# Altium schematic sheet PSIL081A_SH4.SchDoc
size 558 x 431 mm; Date: Not shown in title block; ApprovedBy: Not shown in title block; CheckedBy: Not shown in title block; Author: Not shown in title block; CompanyName: Not shown in title block; Engineer: Not shown in title block; Organization: Not shown in title block; Address1: Not shown in title block; Address2: Not shown in title block; Address3: Not shown in title block; Address4: Not shown in title block; DocumentNumber: 4; Revision: Use project parameter SCH_Rev; SheetNumber: 4; SheetTotal: 5; PageSetup: Record=PageOptions¦CenterHorizontal=True¦CenterVertical=True¦PrintScale=1.00¦XCorrection=1.00¦YCorrection=1.00¦PrintKind=0¦BorderSize=5000000¦LeftOffset=0¦BottomOffset=0¦Orientation=2¦PaperLength=1000¦PaperWidth=1000¦Scale=100¦PaperSource=15¦PrintQuality=600¦MediaType=1¦DitherType=10¦PaperKind=Letter¦PrintScaleMode=1
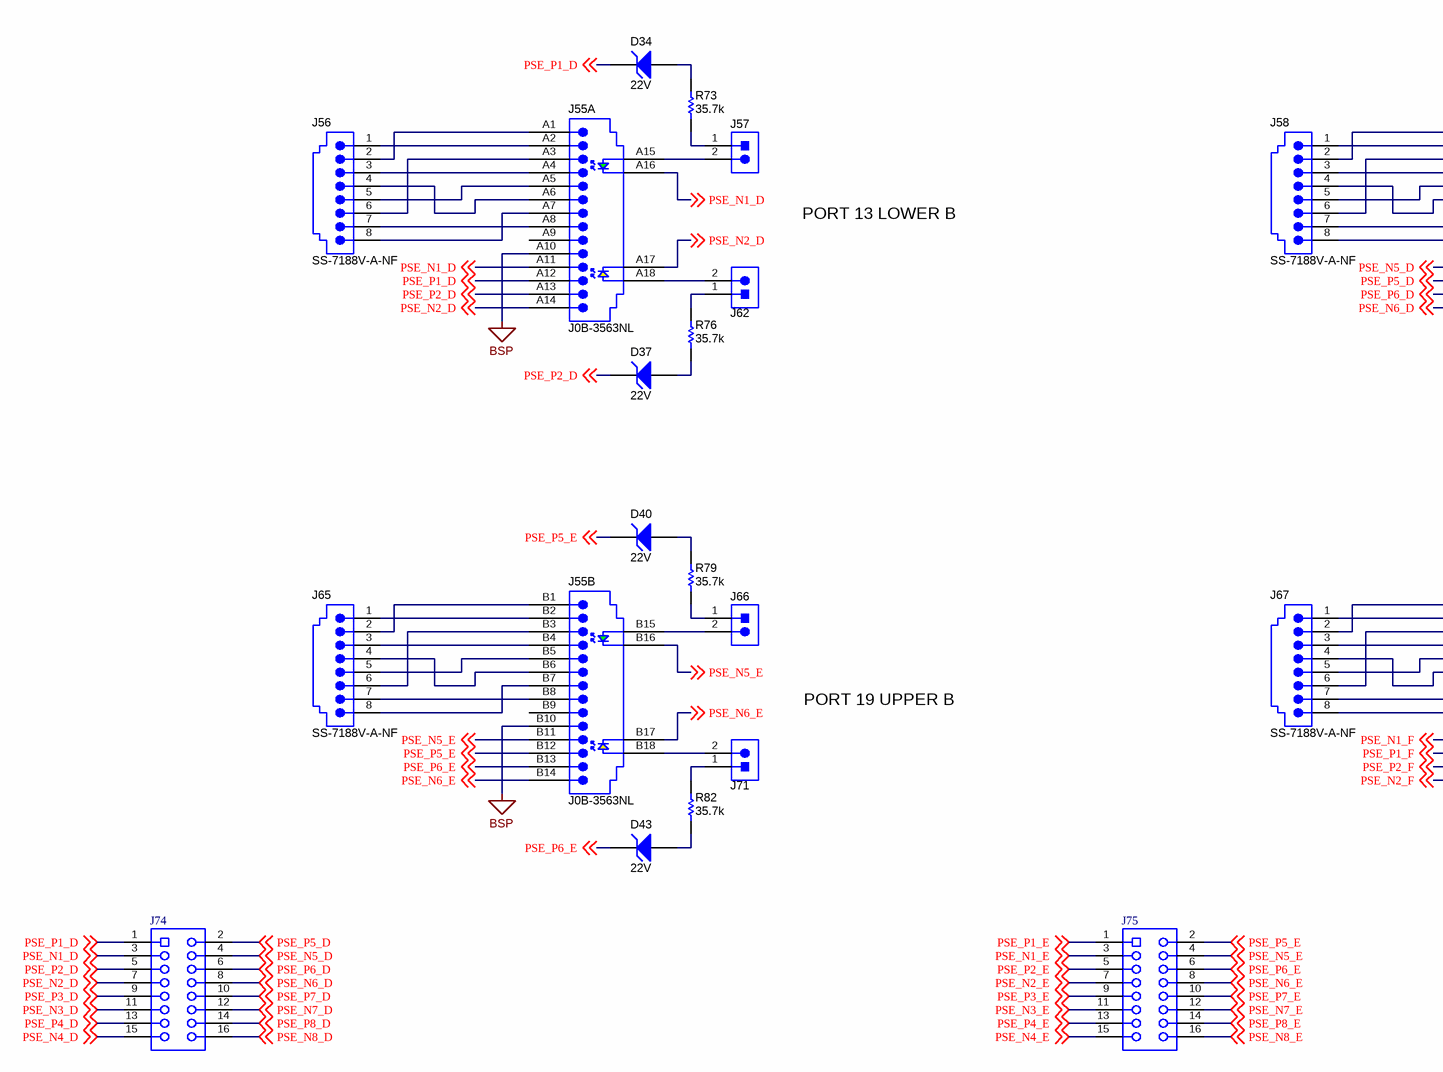
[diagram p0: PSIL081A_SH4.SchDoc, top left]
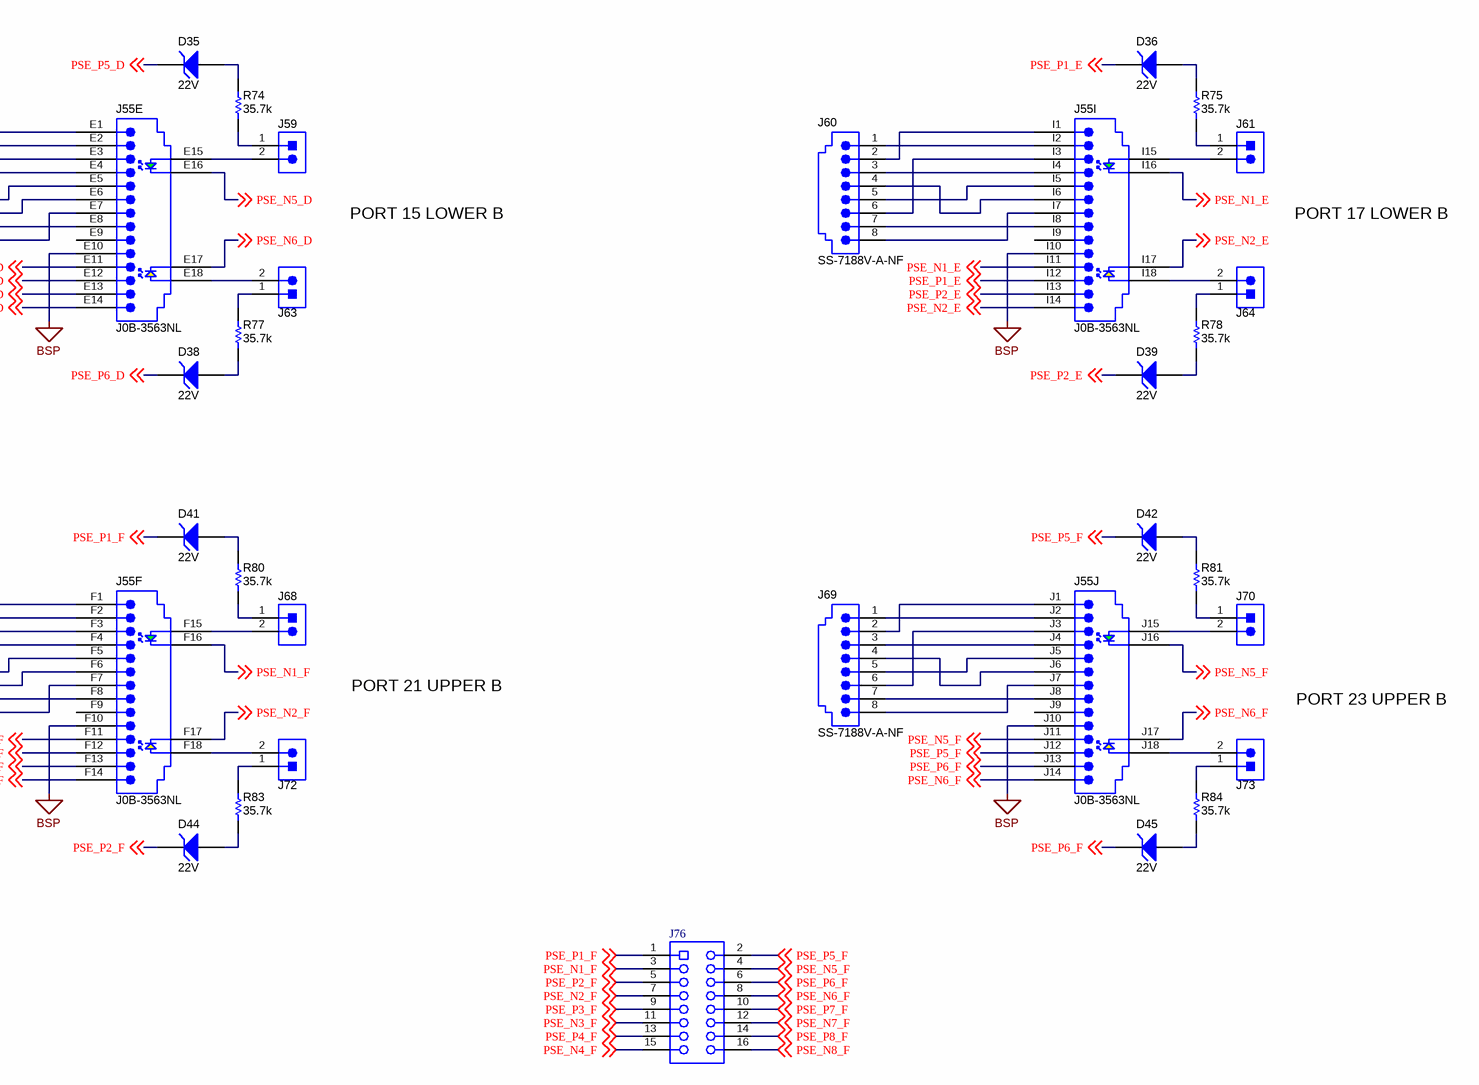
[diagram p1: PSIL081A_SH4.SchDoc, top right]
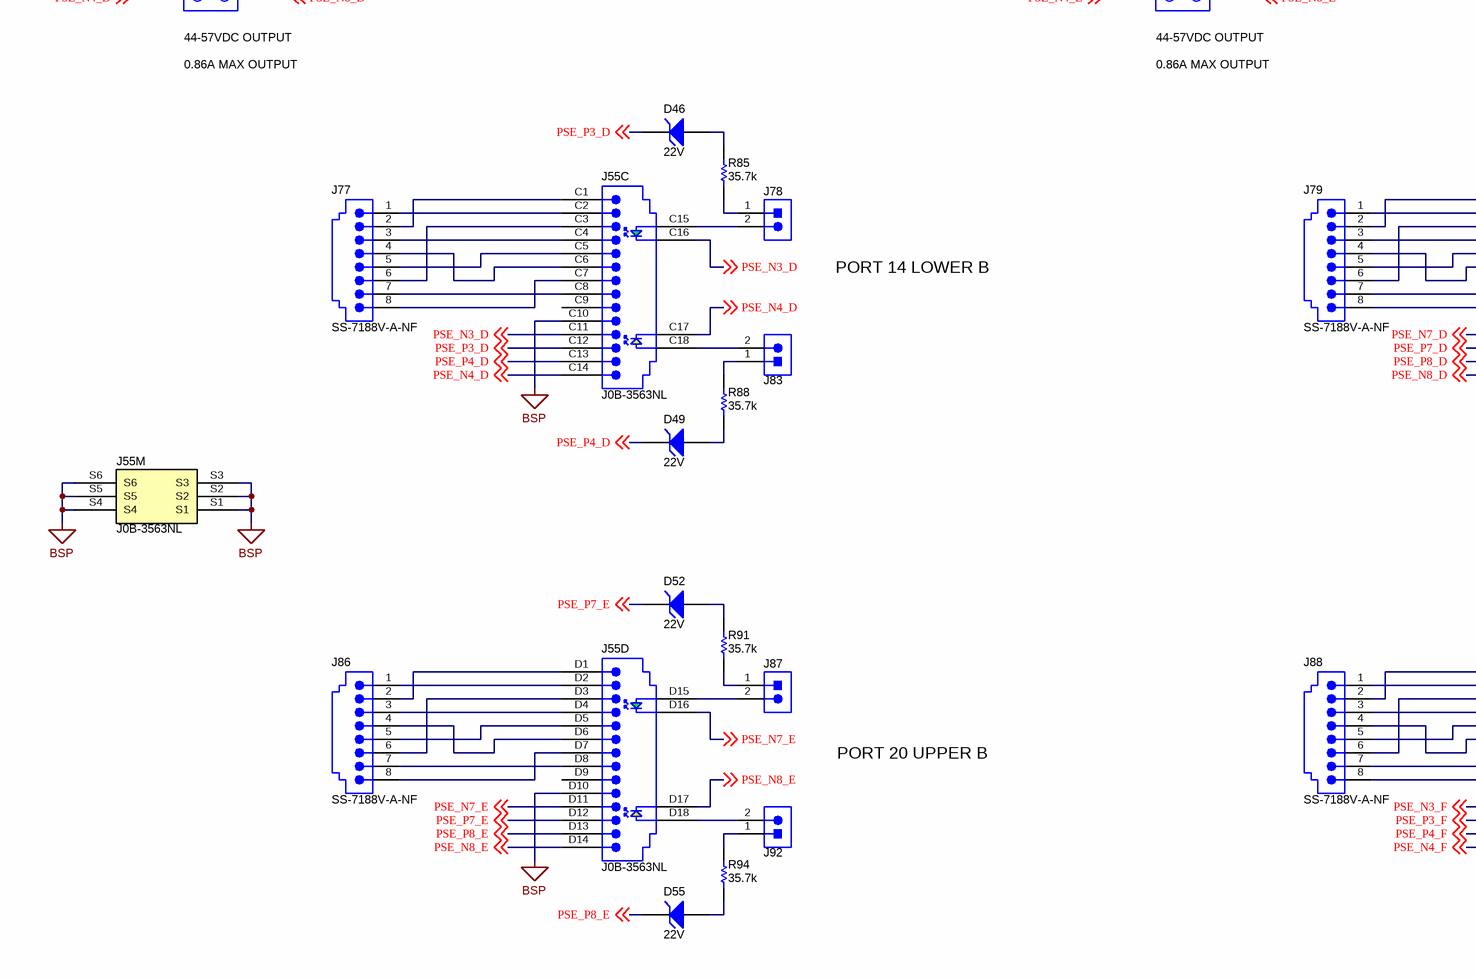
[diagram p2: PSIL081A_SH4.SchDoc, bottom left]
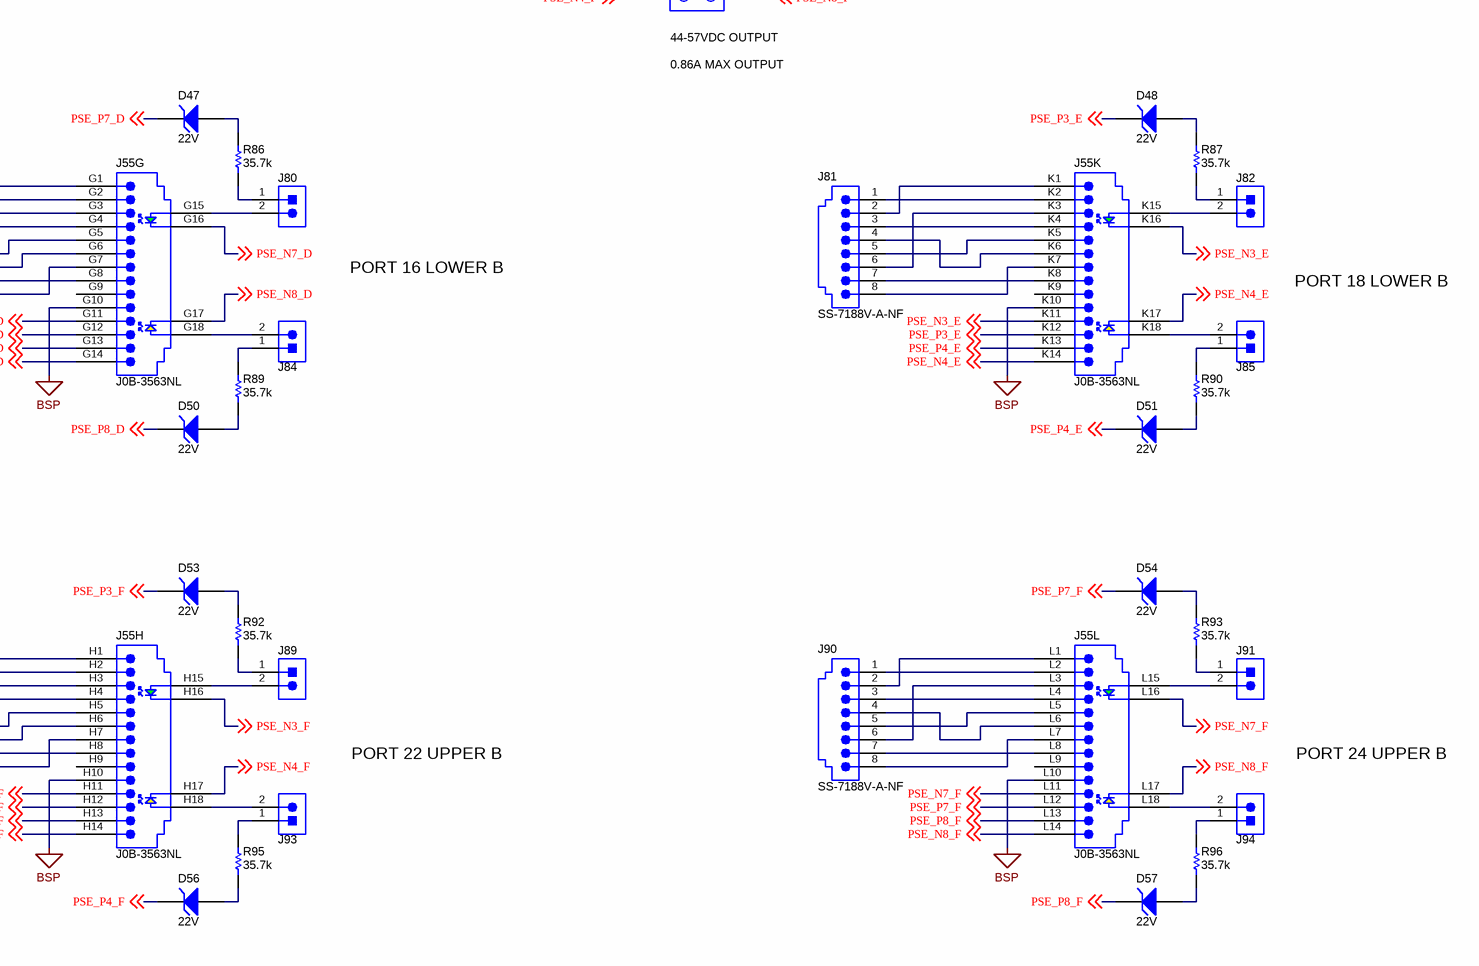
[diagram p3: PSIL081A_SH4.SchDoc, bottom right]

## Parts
D34  Vz_V: 22V  [SOD-123]  (hidden comment: MMSZ5251B-7-F)
D35  Vz_V: 22V  [SOD-123]  (hidden comment: MMSZ5251B-7-F)
D36  Vz_V: 22V  [SOD-123]  (hidden comment: MMSZ5251B-7-F)
D37  Vz_V: 22V  [SOD-123]  (hidden comment: MMSZ5251B-7-F)
D38  Vz_V: 22V  [SOD-123]  (hidden comment: MMSZ5251B-7-F)
D39  Vz_V: 22V  [SOD-123]  (hidden comment: MMSZ5251B-7-F)
D40  Vz_V: 22V  [SOD-123]  (hidden comment: MMSZ5251B-7-F)
D41  Vz_V: 22V  [SOD-123]  (hidden comment: MMSZ5251B-7-F)
D42  Vz_V: 22V  [SOD-123]  (hidden comment: MMSZ5251B-7-F)
D43  Vz_V: 22V  [SOD-123]  (hidden comment: MMSZ5251B-7-F)
D44  Vz_V: 22V  [SOD-123]  (hidden comment: MMSZ5251B-7-F)
D45  Vz_V: 22V  [SOD-123]  (hidden comment: MMSZ5251B-7-F)
D46  Vz_V: 22V  [SOD-123]  (hidden comment: MMSZ5251B-7-F)
D47  Vz_V: 22V  [SOD-123]  (hidden comment: MMSZ5251B-7-F)
D48  Vz_V: 22V  [SOD-123]  (hidden comment: MMSZ5251B-7-F)
D49  Vz_V: 22V  [SOD-123]  (hidden comment: MMSZ5251B-7-F)
D50  Vz_V: 22V  [SOD-123]  (hidden comment: MMSZ5251B-7-F)
D51  Vz_V: 22V  [SOD-123]  (hidden comment: MMSZ5251B-7-F)
D52  Vz_V: 22V  [SOD-123]  (hidden comment: MMSZ5251B-7-F)
D53  Vz_V: 22V  [SOD-123]  (hidden comment: MMSZ5251B-7-F)
D54  Vz_V: 22V  [SOD-123]  (hidden comment: MMSZ5251B-7-F)
D55  Vz_V: 22V  [SOD-123]  (hidden comment: MMSZ5251B-7-F)
D56  Vz_V: 22V  [SOD-123]  (hidden comment: MMSZ5251B-7-F)
D57  Vz_V: 22V  [SOD-123]  (hidden comment: MMSZ5251B-7-F)
J55  J0B-3563NL  [Pulse_J0B-3563NL]  (parts A,B,C,D,E,F,G,H,I,J,K,L,M of 13)
J56  SS-7188V-A-NF  [CONN_SS-7188V-A-NF]
J57  TSW-102-07-G-S  [TSW-102-07-G-S]  (value not drawn)
J58  SS-7188V-A-NF  [CONN_SS-7188V-A-NF]
J59  TSW-102-07-G-S  [TSW-102-07-G-S]  (value not drawn)
J60  SS-7188V-A-NF  [CONN_SS-7188V-A-NF]
J61  TSW-102-07-G-S  [TSW-102-07-G-S]  (value not drawn)
J62  TSW-102-07-G-S  [TSW-102-07-G-S]  (value not drawn)
J63  TSW-102-07-G-S  [TSW-102-07-G-S]  (value not drawn)
J64  TSW-102-07-G-S  [TSW-102-07-G-S]  (value not drawn)
J65  SS-7188V-A-NF  [CONN_SS-7188V-A-NF]
J66  TSW-102-07-G-S  [TSW-102-07-G-S]  (value not drawn)
J67  SS-7188V-A-NF  [CONN_SS-7188V-A-NF]
J68  TSW-102-07-G-S  [TSW-102-07-G-S]  (value not drawn)
J69  SS-7188V-A-NF  [CONN_SS-7188V-A-NF]
J70  TSW-102-07-G-S  [TSW-102-07-G-S]  (value not drawn)
J71  TSW-102-07-G-S  [TSW-102-07-G-S]  (value not drawn)
J72  TSW-102-07-G-S  [TSW-102-07-G-S]  (value not drawn)
J73  TSW-102-07-G-S  [TSW-102-07-G-S]  (value not drawn)
J74  SSW-108-21-G-D  [Samtec_SSW-108-01-x-D]  (value not drawn)
J75  SSW-108-21-G-D  [Samtec_SSW-108-01-x-D]  (value not drawn)
J76  SSW-108-21-G-D  [Samtec_SSW-108-01-x-D]  (value not drawn)
J77  SS-7188V-A-NF  [CONN_SS-7188V-A-NF]
J78  TSW-102-07-G-S  [TSW-102-07-G-S]  (value not drawn)
J79  SS-7188V-A-NF  [CONN_SS-7188V-A-NF]
J80  TSW-102-07-G-S  [TSW-102-07-G-S]  (value not drawn)
J81  SS-7188V-A-NF  [CONN_SS-7188V-A-NF]
J82  TSW-102-07-G-S  [TSW-102-07-G-S]  (value not drawn)
J83  TSW-102-07-G-S  [TSW-102-07-G-S]  (value not drawn)
J84  TSW-102-07-G-S  [TSW-102-07-G-S]  (value not drawn)
J85  TSW-102-07-G-S  [TSW-102-07-G-S]  (value not drawn)
J86  SS-7188V-A-NF  [CONN_SS-7188V-A-NF]
J87  TSW-102-07-G-S  [TSW-102-07-G-S]  (value not drawn)
J88  SS-7188V-A-NF  [CONN_SS-7188V-A-NF]
J89  TSW-102-07-G-S  [TSW-102-07-G-S]  (value not drawn)
J90  SS-7188V-A-NF  [CONN_SS-7188V-A-NF]
J91  TSW-102-07-G-S  [TSW-102-07-G-S]  (value not drawn)
J92  TSW-102-07-G-S  [TSW-102-07-G-S]  (value not drawn)
J93  TSW-102-07-G-S  [TSW-102-07-G-S]  (value not drawn)
J94  TSW-102-07-G-S  [TSW-102-07-G-S]  (value not drawn)
R73  ValueDisplayed: 35.7k  [0603]  (hidden comment: CRCW060335K7FKEA)
R74  ValueDisplayed: 35.7k  [0603]  (hidden comment: CRCW060335K7FKEA)
R75  ValueDisplayed: 35.7k  [0603]  (hidden comment: CRCW060335K7FKEA)
R76  ValueDisplayed: 35.7k  [0603]  (hidden comment: CRCW060335K7FKEA)
R77  ValueDisplayed: 35.7k  [0603]  (hidden comment: CRCW060335K7FKEA)
R78  ValueDisplayed: 35.7k  [0603]  (hidden comment: CRCW060335K7FKEA)
R79  ValueDisplayed: 35.7k  [0603]  (hidden comment: CRCW060335K7FKEA)
R80  ValueDisplayed: 35.7k  [0603]  (hidden comment: CRCW060335K7FKEA)
R81  ValueDisplayed: 35.7k  [0603]  (hidden comment: CRCW060335K7FKEA)
R82  ValueDisplayed: 35.7k  [0603]  (hidden comment: CRCW060335K7FKEA)
R83  ValueDisplayed: 35.7k  [0603]  (hidden comment: CRCW060335K7FKEA)
R84  ValueDisplayed: 35.7k  [0603]  (hidden comment: CRCW060335K7FKEA)
R85  ValueDisplayed: 35.7k  [0603]  (hidden comment: CRCW060335K7FKEA)
R86  ValueDisplayed: 35.7k  [0603]  (hidden comment: CRCW060335K7FKEA)
R87  ValueDisplayed: 35.7k  [0603]  (hidden comment: CRCW060335K7FKEA)
R88  ValueDisplayed: 35.7k  [0603]  (hidden comment: CRCW060335K7FKEA)
R89  ValueDisplayed: 35.7k  [0603]  (hidden comment: CRCW060335K7FKEA)
R90  ValueDisplayed: 35.7k  [0603]  (hidden comment: CRCW060335K7FKEA)
R91  ValueDisplayed: 35.7k  [0603]  (hidden comment: CRCW060335K7FKEA)
R92  ValueDisplayed: 35.7k  [0603]  (hidden comment: CRCW060335K7FKEA)
R93  ValueDisplayed: 35.7k  [0603]  (hidden comment: CRCW060335K7FKEA)
R94  ValueDisplayed: 35.7k  [0603]  (hidden comment: CRCW060335K7FKEA)
R95  ValueDisplayed: 35.7k  [0603]  (hidden comment: CRCW060335K7FKEA)
R96  ValueDisplayed: 35.7k  [0603]  (hidden comment: CRCW060335K7FKEA)

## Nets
BSP: J55.A10 J55.B10 J55.C10 J55.D10 J55.E10 J55.F10 J55.G10 J55.H10 J55.I10 J55.J10 J55.K10 J55.L10 J55.S1 J55.S2 J55.S3 J55.S4 J55.S5 J55.S6
PSE_N1_D: J55.A11 J55.A16 J74.3 ; off-sheet PSE_N1_D
PSE_N1_E: J55.I11 J55.I16 J75.3 ; off-sheet PSE_N1_E
PSE_N1_F: J55.F11 J55.F16 J76.3 ; off-sheet PSE_N1_F
PSE_N2_D: J55.A14 J55.A17 J74.7 ; off-sheet PSE_N2_D
PSE_N2_E: J55.I14 J55.I17 J75.7 ; off-sheet PSE_N2_E
PSE_N2_F: J55.F14 J55.F17 J76.7 ; off-sheet PSE_N2_F
PSE_N3_D: J55.C11 J55.C16 J74.11 ; off-sheet PSE_N3_D
PSE_N3_E: J55.K11 J55.K16 J75.11 ; off-sheet PSE_N3_E
PSE_N3_F: J55.H11 J55.H16 J76.11 ; off-sheet PSE_N3_F
PSE_N4_D: J55.C14 J55.C17 J74.15 ; off-sheet PSE_N4_D
PSE_N4_E: J55.K14 J55.K17 J75.15 ; off-sheet PSE_N4_E
PSE_N4_F: J55.H14 J55.H17 J76.15 ; off-sheet PSE_N4_F
PSE_N5_D: J55.E11 J55.E16 J74.4 ; off-sheet PSE_N5_D
PSE_N5_E: J55.B11 J55.B16 J75.4 ; off-sheet PSE_N5_E
PSE_N5_F: J55.J11 J55.J16 J76.4 ; off-sheet PSE_N5_F
PSE_N6_D: J55.E14 J55.E17 J74.8 ; off-sheet PSE_N6_D
PSE_N6_E: J55.B14 J55.B17 J75.8 ; off-sheet PSE_N6_E
PSE_N6_F: J55.J14 J55.J17 J76.8 ; off-sheet PSE_N6_F
PSE_N7_D: J55.G11 J55.G16 J74.12 ; off-sheet PSE_N7_D
PSE_N7_E: J55.D11 J55.D16 J75.12 ; off-sheet PSE_N7_E
PSE_N7_F: J55.L11 J55.L16 J76.12 ; off-sheet PSE_N7_F
PSE_N8_D: J55.G14 J55.G17 J74.16 ; off-sheet PSE_N8_D
PSE_N8_E: J55.D14 J55.D17 J75.16 ; off-sheet PSE_N8_E
PSE_N8_F: J55.L14 J55.L17 J76.16 ; off-sheet PSE_N8_F
PSE_P1_D: D34.1(K) J55.A12 J74.1 ; off-sheet PSE_P1_D
PSE_P1_E: D36.1(K) J55.I12 J75.1 ; off-sheet PSE_P1_E
PSE_P1_F: D41.1(K) J55.F12 J76.1 ; off-sheet PSE_P1_F
PSE_P2_D: D37.1(K) J55.A13 J74.5 ; off-sheet PSE_P2_D
PSE_P2_E: D39.1(K) J55.I13 J75.5 ; off-sheet PSE_P2_E
PSE_P2_F: D44.1(K) J55.F13 J76.5 ; off-sheet PSE_P2_F
PSE_P3_D: D46.1(K) J55.C12 J74.9 ; off-sheet PSE_P3_D
PSE_P3_E: D48.1(K) J55.K12 J75.9 ; off-sheet PSE_P3_E
PSE_P3_F: D53.1(K) J55.H12 J76.9 ; off-sheet PSE_P3_F
PSE_P4_D: D49.1(K) J55.C13 J74.13 ; off-sheet PSE_P4_D
PSE_P4_E: D51.1(K) J55.K13 J75.13 ; off-sheet PSE_P4_E
PSE_P4_F: D56.1(K) J55.H13 J76.13 ; off-sheet PSE_P4_F
PSE_P5_D: D35.1(K) J55.E12 J74.2 ; off-sheet PSE_P5_D
PSE_P5_E: D40.1(K) J55.B12 J75.2 ; off-sheet PSE_P5_E
PSE_P5_F: D42.1(K) J55.J12 J76.2 ; off-sheet PSE_P5_F
PSE_P6_D: D38.1(K) J55.E13 J74.6 ; off-sheet PSE_P6_D
PSE_P6_E: D43.1(K) J55.B13 J75.6 ; off-sheet PSE_P6_E
PSE_P6_F: D45.1(K) J55.J13 J76.6 ; off-sheet PSE_P6_F
PSE_P7_D: D47.1(K) J55.G12 J74.10 ; off-sheet PSE_P7_D
PSE_P7_E: D52.1(K) J55.D12 J75.10 ; off-sheet PSE_P7_E
PSE_P7_F: D54.1(K) J55.L12 J76.10 ; off-sheet PSE_P7_F
PSE_P8_D: D50.1(K) J55.G13 J74.14 ; off-sheet PSE_P8_D
PSE_P8_E: D55.1(K) J55.D13 J75.14 ; off-sheet PSE_P8_E
PSE_P8_F: D57.1(K) J55.L13 J76.14 ; off-sheet PSE_P8_F
NetD34_2: D34.2(A) R73.1
NetD35_2: D35.2(A) R74.1
NetD36_2: D36.2(A) R75.1
NetD37_2: D37.2(A) R76.2
NetD38_2: D38.2(A) R77.2
NetD39_2: D39.2(A) R78.2
NetD40_2: D40.2(A) R79.1
NetD41_2: D41.2(A) R80.1
NetD42_2: D42.2(A) R81.1
NetD43_2: D43.2(A) R82.2
NetD44_2: D44.2(A) R83.2
NetD45_2: D45.2(A) R84.2
NetD46_2: D46.2(A) R85.1
NetD47_2: D47.2(A) R86.1
NetD48_2: D48.2(A) R87.1
NetD49_2: D49.2(A) R88.2
NetD50_2: D50.2(A) R89.2
NetD51_2: D51.2(A) R90.2
NetD52_2: D52.2(A) R91.1
NetD53_2: D53.2(A) R92.1
NetD54_2: D54.2(A) R93.1
NetD55_2: D55.2(A) R94.2
NetD56_2: D56.2(A) R95.2
NetD57_2: D57.2(A) R96.2
NetJ55_A1: J55.A1 J56.2
NetJ55_A2: J55.A2 J56.1
NetJ55_A3: J55.A3 J56.6
NetJ55_A4: J55.A4 J56.3
NetJ55_A5: J55.A5 J56.5
NetJ55_A6: J55.A6 J56.4
NetJ55_A7: J55.A7 J56.8
NetJ55_A8: J55.A8 J56.7
NetJ55_A15: J55.A15 J57.2
NetJ55_A18: J55.A18 J62.2
NetJ55_B1: J55.B1 J65.2
NetJ55_B2: J55.B2 J65.1
NetJ55_B3: J55.B3 J65.6
NetJ55_B4: J55.B4 J65.3
NetJ55_B5: J55.B5 J65.5
NetJ55_B6: J55.B6 J65.4
NetJ55_B7: J55.B7 J65.8
NetJ55_B8: J55.B8 J65.7
NetJ55_B15: J55.B15 J66.2
NetJ55_B18: J55.B18 J71.2
NetJ55_C1: J55.C1 J77.2
NetJ55_C2: J55.C2 J77.1
NetJ55_C3: J55.C3 J77.6
NetJ55_C4: J55.C4 J77.3
NetJ55_C5: J55.C5 J77.5
NetJ55_C6: J55.C6 J77.4
NetJ55_C7: J55.C7 J77.8
NetJ55_C8: J55.C8 J77.7
NetJ55_C15: J55.C15 J78.2
NetJ55_C18: J55.C18 J83.2
NetJ55_D1: J55.D1 J86.2
NetJ55_D2: J55.D2 J86.1
NetJ55_D3: J55.D3 J86.6
NetJ55_D4: J55.D4 J86.3
NetJ55_D5: J55.D5 J86.5
NetJ55_D6: J55.D6 J86.4
NetJ55_D7: J55.D7 J86.8
NetJ55_D8: J55.D8 J86.7
NetJ55_D15: J55.D15 J87.2
NetJ55_D18: J55.D18 J92.2
NetJ55_E1: J55.E1 J58.2
NetJ55_E2: J55.E2 J58.1
NetJ55_E3: J55.E3 J58.6
NetJ55_E4: J55.E4 J58.3
NetJ55_E5: J55.E5 J58.5
NetJ55_E6: J55.E6 J58.4
NetJ55_E7: J55.E7 J58.8
NetJ55_E8: J55.E8 J58.7
NetJ55_E15: J55.E15 J59.2
NetJ55_E18: J55.E18 J63.2
NetJ55_F1: J55.F1 J67.2
NetJ55_F2: J55.F2 J67.1
NetJ55_F3: J55.F3 J67.6
NetJ55_F4: J55.F4 J67.3
NetJ55_F5: J55.F5 J67.5
NetJ55_F6: J55.F6 J67.4
NetJ55_F7: J55.F7 J67.8
NetJ55_F8: J55.F8 J67.7
NetJ55_F15: J55.F15 J68.2
NetJ55_F18: J55.F18 J72.2
NetJ55_G1: J55.G1 J79.2
NetJ55_G2: J55.G2 J79.1
NetJ55_G3: J55.G3 J79.6
NetJ55_G4: J55.G4 J79.3
NetJ55_G5: J55.G5 J79.5
NetJ55_G6: J55.G6 J79.4
NetJ55_G7: J55.G7 J79.8
NetJ55_G8: J55.G8 J79.7
NetJ55_G15: J55.G15 J80.2
NetJ55_G18: J55.G18 J84.2
NetJ55_H1: J55.H1 J88.2
NetJ55_H2: J55.H2 J88.1
NetJ55_H3: J55.H3 J88.6
NetJ55_H4: J55.H4 J88.3
NetJ55_H5: J55.H5 J88.5
NetJ55_H6: J55.H6 J88.4
NetJ55_H7: J55.H7 J88.8
NetJ55_H8: J55.H8 J88.7
NetJ55_H15: J55.H15 J89.2
NetJ55_H18: J55.H18 J93.2
NetJ55_I1: J55.I1 J60.2
NetJ55_I2: J55.I2 J60.1
NetJ55_I3: J55.I3 J60.6
NetJ55_I4: J55.I4 J60.3
NetJ55_I5: J55.I5 J60.5
NetJ55_I6: J55.I6 J60.4
NetJ55_I7: J55.I7 J60.8
NetJ55_I8: J55.I8 J60.7
NetJ55_I15: J55.I15 J61.2
NetJ55_I18: J55.I18 J64.2
NetJ55_J1: J55.J1 J69.2
NetJ55_J2: J55.J2 J69.1
NetJ55_J3: J55.J3 J69.6
NetJ55_J4: J55.J4 J69.3
NetJ55_J5: J55.J5 J69.5
NetJ55_J6: J55.J6 J69.4
NetJ55_J7: J55.J7 J69.8
NetJ55_J8: J55.J8 J69.7
NetJ55_J15: J55.J15 J70.2
NetJ55_J18: J55.J18 J73.2
NetJ55_K1: J55.K1 J81.2
NetJ55_K2: J55.K2 J81.1
NetJ55_K3: J55.K3 J81.6
NetJ55_K4: J55.K4 J81.3
NetJ55_K5: J55.K5 J81.5
NetJ55_K6: J55.K6 J81.4
NetJ55_K7: J55.K7 J81.8
NetJ55_K8: J55.K8 J81.7
NetJ55_K15: J55.K15 J82.2
NetJ55_K18: J55.K18 J85.2
NetJ55_L1: J55.L1 J90.2
NetJ55_L2: J55.L2 J90.1
NetJ55_L3: J55.L3 J90.6
NetJ55_L4: J55.L4 J90.3
NetJ55_L5: J55.L5 J90.5
NetJ55_L6: J55.L6 J90.4
NetJ55_L7: J55.L7 J90.8
NetJ55_L8: J55.L8 J90.7
NetJ55_L15: J55.L15 J91.2
NetJ55_L18: J55.L18 J94.2
NetJ57_1: J57.1 R73.2
NetJ59_1: J59.1 R74.2
NetJ61_1: J61.1 R75.2
NetJ62_1: J62.1 R76.1
NetJ63_1: J63.1 R77.1
NetJ64_1: J64.1 R78.1
NetJ66_1: J66.1 R79.2
NetJ68_1: J68.1 R80.2
NetJ70_1: J70.1 R81.2
NetJ71_1: J71.1 R82.1
NetJ72_1: J72.1 R83.1
NetJ73_1: J73.1 R84.1
NetJ78_1: J78.1 R85.2
NetJ80_1: J80.1 R86.2
NetJ82_1: J82.1 R87.2
NetJ83_1: J83.1 R88.1
NetJ84_1: J84.1 R89.1
NetJ85_1: J85.1 R90.1
NetJ87_1: J87.1 R91.2
NetJ89_1: J89.1 R92.2
NetJ91_1: J91.1 R93.2
NetJ92_1: J92.1 R94.1
NetJ93_1: J93.1 R95.1
NetJ94_1: J94.1 R96.1

Not connected (* = marked no-connect by the designer): J55 A9 B9 C9 D9 E9 F9 G9 H9 I9 J9 K9 L9

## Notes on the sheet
- PORT 13 LOWER B
- PORT 15 LOWER B
- PORT 17 LOWER B
- PORT 21 UPPER B
- PORT 19 UPPER B
- PORT 23 UPPER B
- (near J74) 44-57VDC OUTPUT
- (near J75) 44-57VDC OUTPUT
- (near J76) 44-57VDC OUTPUT
- 0.86A MAX OUTPUT
- PORT 14 LOWER B
- PORT 16 LOWER B
- PORT 18 LOWER B
- PORT 20 UPPER B
- PORT 22 UPPER B
- PORT 24 UPPER B

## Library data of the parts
D34-D57 = CMP-0005757-2: Diode, Zener, 22 V, 500 mW, SOD-123; Manufacturer: Diodes Inc.; Power_W: 500mW; SizeAreaWB_mm2: 13.095; Value1: 0.5W; RJA_CperW: 350; U/M: EA; Value: 22V; SizeZ_mm: 1.35; SizeX_mm: 3.85; SizeY_mm: 1.7; SizeArea_mm2: 6.545; AEC Category: Q101
J55 = CMP-0081711-4: 12 Port RJ45, R/A, TH; Manufacturer: Pulse Engineering; Gender: Female; ContactFinish: Gold
J56 J58 J60 J65 J67 J69 J77 J79 J81 J86 J88 J90 = CMP-0055855-1: RJ45, Vertical, TH; Manufacturer: Stewart Connector; CT: TRUE; Green_REACh: Incomplete; CNHeader: FALSE; Green_Lifecycle: Not Set
J57 J59 J61-J64 J66 J68 J70-J73 J78 J80 J82-J85 J87 J89 J91-J94 = CMP-0075405-2: Header, 100mil, 2x1, Gold, TH; Manufacturer: Samtec; Pitch_mm: 2.54; Cert_VDE: N; Gender: Male; Cert_CSA: Y; Voltage_V: 550V; Green_REACh: Passed; Current_A: 6.3A; Green_Lifecycle: Active; Row_Count: 1
J74-J76 = CMP-0750077-1: Receptacle, 2.54mm, 8x2, Gold, TH; Manufacturer: Samtec; Pitch_mm: 2.54; Gender: Female; Current_A: 4.7A; Cert_UL: Y; Row_Count: 2; Voltage_V: 655V
R73-R96 = CMP-0022352-4: RES, 35.7 k, 1%, 0.1 W, AEC-Q200 Grade 0, 0603; Manufacturer: Vishay-Dale; Power_W: 100mW; TempCo: 100 ppm/C; Value_Code: 35k7; Value: 35.7k; EIA_Code: E96; SizeX_mm: 1.6; SizeY_mm: 0.8; SizeZ_mm: 1; Value2: 0.1W; SizeArea_mm2: 1.28; AEC Qualified: Y; VDC_V: 75V; AEC Category: Q200; AEC Grade: 0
